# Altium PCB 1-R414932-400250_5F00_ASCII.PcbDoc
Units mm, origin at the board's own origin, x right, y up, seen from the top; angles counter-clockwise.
Board outline 46.04 x 15.24 mm, 2 copper layers (Top Layer, Bottom Layer), stack 1.97 mm thick; 97 components, 64 nets, 370 pads, 105 vias.
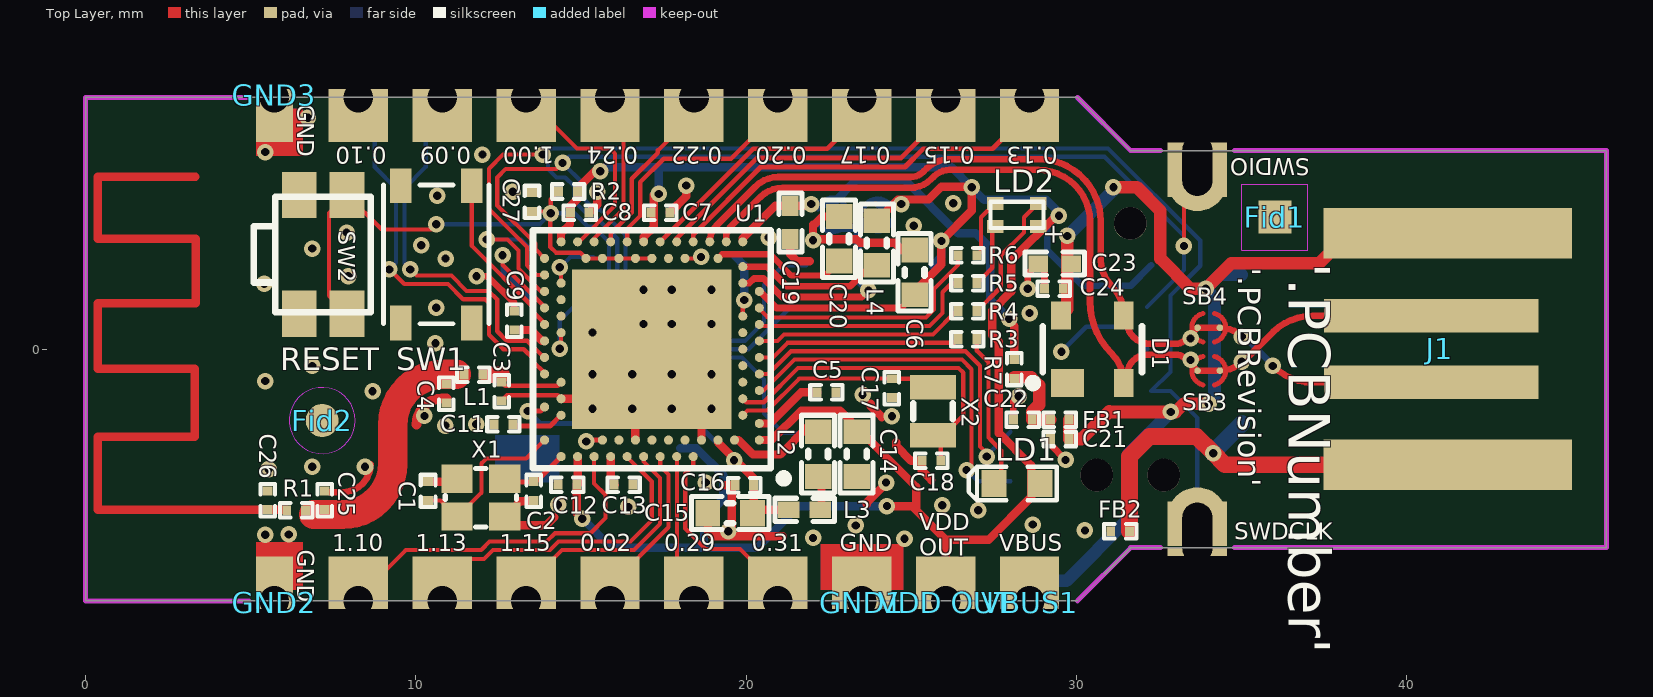
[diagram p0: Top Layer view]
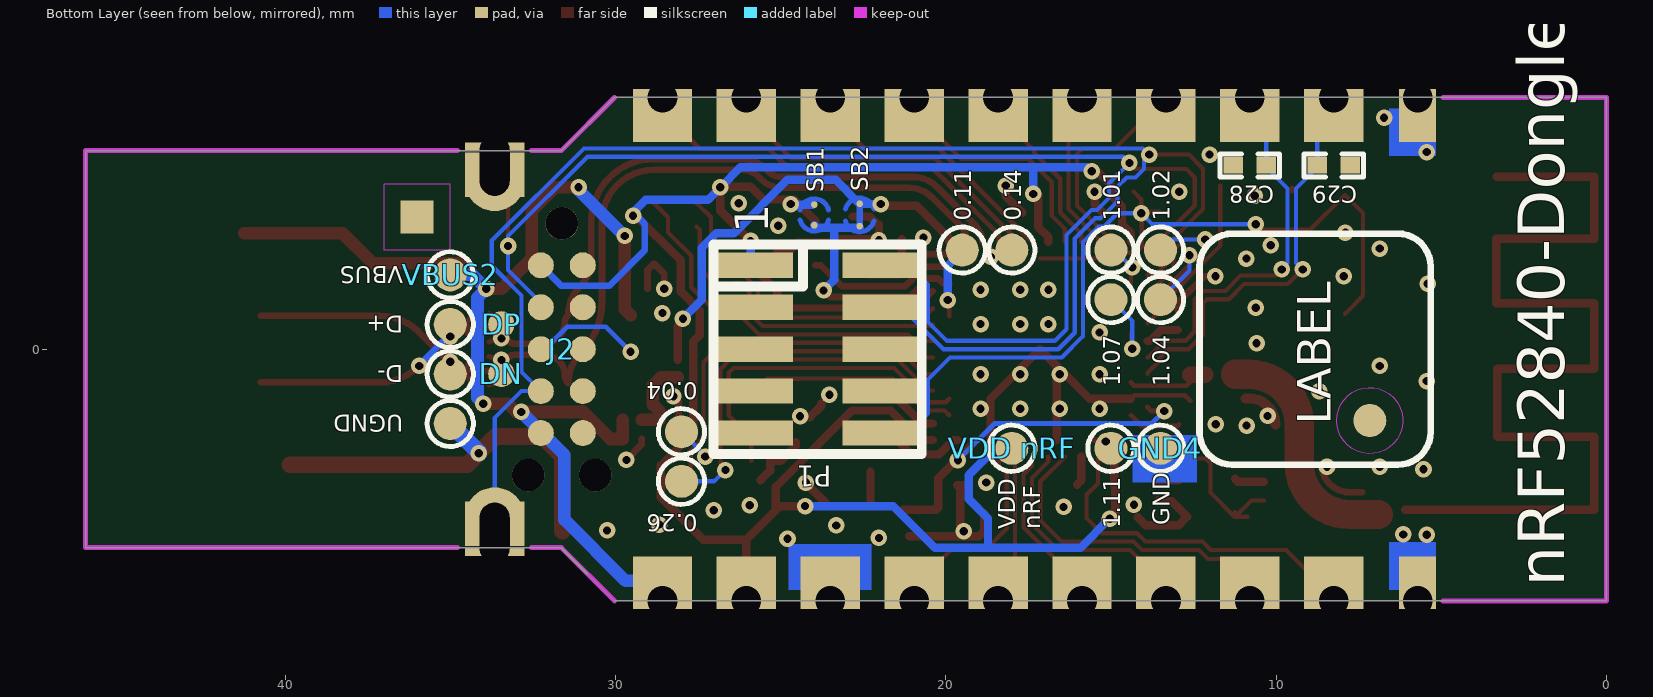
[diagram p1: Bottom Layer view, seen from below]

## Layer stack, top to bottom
Top Solder: solder mask 0.05, Solder Resist Halogen-Free, Dk 3.5
Top Layer: signal copper 0.035
Dielectric1: core 1.9, FR-4 Halogen-Free, Dk 4.8
Bottom Layer: signal copper 0.035
Bottom Solder: solder mask 0.05, Solder Resist Halogen-Free, Dk 3.5

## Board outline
0,-7.62 0,7.62 30.027,7.62 31.637,6.01 46.039,6.01 46.039,-6.01 31.637,-6.01 30.027,-7.62

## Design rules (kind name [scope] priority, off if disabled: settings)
AssemblyTestPointUsage [All] p0: scope1count=1 scope1_0_kind=Board scope1_0_value=Board scope2count=1 scope2_0_kind=Board scope2_0_value=Board commentlength=0
AssemblyTestpoint [All] p0: scope1count=1 scope1_0_kind=Board scope1_0_value=Board scope2count=1 scope2_0_kind=Board scope2_0_value=Board commentlength=0
Clearance [All] p0: scope1count=1 scope1_0_kind=Board scope1_0_value=Board scope2count=1 scope2_0_kind=Board scope2_0_value=Board commentlength=0 gap=0.127
Clearance SB_Clearance [All] p0: scope1count=1 scope1_0_kind=Footprint scope1_0_value=Solderbridge scope2count=1 scope2_0_kind=Board scope2_0_value=Board commentlength=0 gap=0.127
Clearance Polygon_Clearance [All] p0 off: scope1count=1 scope1_0_kind=Board scope1_0_value=Board scope2count=1 scope2_0_kind=Board scope2_0_value=Board commentlength=190 gap=0.203 // Protel DXP Scope 1 Expression Was: (InNamedPolygon('Top_Layer-GND')) or (InNamedPolygon('Bottom_Layer-GND')) or (InNamedPolygon('Mid_Layer_1-GND')) or (InNamedPolygon('Mid_Layer_2-GND'))
Clearance NPTH [All] p0 off: scope1count=1 scope1_0_kind=Board scope1_0_value=Board scope2count=1 scope2_0_kind=Board scope2_0_value=Board commentlength=71 gap=0.229 // Protel DXP Scope 1 Expression Was: Not PadIsPlated And HoleSize > 0
Clearance ANT_Clerance [All] p0 off: scope1count=1 scope1_0_kind=Board scope1_0_value=Board scope2count=1 scope2_0_kind=Board scope2_0_value=Board commentlength=66 gap=0.127 // Protel DXP Scope 1 Expression Was: InNet('ANT') or InNet('RF')
Clearance ANT_Clerance [InNet('ANT') or InNet('RF')] p1: gap=0.127 ignorepadtopadclearanceinfootprint=FALSE except(0: Arc-Hole Track-Hole SMDPad-Hole THPad-Hole Via-Hole Fill-Hole Poly-Hole Region-Hole Text-Hole)
Clearance NPTH [Not PadIsPlated And HoleSize > 0] p2: gap=0.229 ignorepadtopadclearanceinfootprint=FALSE except(0: Arc-Hole Track-Hole SMDPad-Hole THPad-Hole Via-Hole Fill-Hole Poly-Hole Region-Hole Text-Hole)
Clearance Polygon_Clearance [(InNamedPolygon('Top_Layer-GND')) or (InNamedPolygon('Bottom_Layer-GND')) or (InNamedPolygon('Mid_Layer_1-GND')) or (InNamedPolygon('Mid_Layer_2-GND'))] p3: gap=0.203 ignorepadtopadclearanceinfootprint=FALSE
Clearance SB_Clearance [HasFootprint('Solderbridge')] p4: gap=0.127 ignorepadtopadclearanceinfootprint=FALSE except(0: Arc-Hole Track-Hole SMDPad-Hole THPad-Hole Via-Hole Fill-Hole Poly-Hole Region-Hole Text-Hole)
Clearance [All] p5: gap=0.127 ignorepadtopadclearanceinfootprint=FALSE
ComponentClearance [All] p0 off: scope1count=1 scope1_0_kind=Board scope1_0_value=Board scope2count=1 scope2_0_kind=Board scope2_0_value=Board commentlength=0 gap=0.254 collisioncheckmode=3
ComponentClearance [All] p1 off: gap=0.254 collisioncheckmode=3 verticalgap=0.254 showdistances=FALSE
DiffPairsRouting [All] p0: scope1count=1 scope1_0_kind=Board scope1_0_value=Board scope2count=1 scope2_0_kind=Board scope2_0_value=Board commentlength=0
DiffPairsRouting [All] p1: maxlimit=0.127 minlimit=0.127 mostfreqgap=0.127 toplayer_minwidth=0.2 toplayer_maxwidth=0.2 toplayer_prefwidth=0.2 bottomlayer_minwidth=0.2 bottomlayer_maxwidth=0.2 bottomlayer_prefwidth=0.2 maxuncoupledlength=12.7
FabricationTestPointUsage TestPointUsage [All] p0: scope1count=1 scope1_0_kind=Board scope1_0_value=Board scope2count=1 scope2_0_kind=Board scope2_0_value=Board commentlength=0 valid=0 allowmultiple=FALSE
FabricationTestPointUsage TestPointUsage [All] p1: valid=0 allowmultiple=FALSE
FabricationTestpoint Testpoint [All] p0: scope1count=1 scope1_0_kind=Board scope1_0_value=Board scope2count=1 scope2_0_kind=Board scope2_0_value=Board commentlength=0 side=3 testpointundercomponent=TRUE minsize=1.016 maxsize=2.54 preferedsize=1.524 minholesize=0 maxholesize=1.016 preferedholesize=0.813 testpointgrid=0.025
FabricationTestpoint Testpoint [All] p1: side=3 testpointundercomponent=TRUE minsize=1.016 maxsize=2.54 preferedsize=1.524 minholesize=0 maxholesize=1.016 preferedholesize=0.813 testpointgrid=0.025 allowsidetop=TRUE allowsidebottom=TRUE usegrid=TRUE gridtolerance=0
FanoutControl Fanout_Default [All] p0: scope1count=1 scope1_0_kind=Board scope1_0_value=Board scope2count=1 scope2_0_kind=Board scope2_0_value=Board commentlength=30 // Fanout_Default (Default Rule)
FanoutControl Fanout_Small [All] p0 off: scope1count=1 scope1_0_kind=Board scope1_0_value=Board scope2count=1 scope2_0_kind=Board scope2_0_value=Board commentlength=84 // Protel DXP Scope 1 Expression Was: (CompPinCount < 5)   Fanout_Small (Default Rule)
FanoutControl Fanout_SOIC [All] p0 off: scope1count=1 scope1_0_kind=Board scope1_0_value=Board scope2count=1 scope2_0_kind=Board scope2_0_value=Board commentlength=71 // Protel DXP Scope 1 Expression Was: IsSOIC   Fanout_SOIC (Default Rule)
FanoutControl Fanout_LCC [All] p0 off: scope1count=1 scope1_0_kind=Board scope1_0_value=Board scope2count=1 scope2_0_kind=Board scope2_0_value=Board commentlength=69 // Protel DXP Scope 1 Expression Was: IsLCC   Fanout_LCC (Default Rule)
FanoutControl Fanout_BGA [All] p0 off: scope1count=1 scope1_0_kind=Board scope1_0_value=Board scope2count=1 scope2_0_kind=Board scope2_0_value=Board commentlength=69 // Protel DXP Scope 1 Expression Was: IsBGA   Fanout_BGA (Default Rule)
Height [All] p0 off: scope1count=1 scope1_0_kind=Board scope1_0_value=Board scope2count=1 scope2_0_kind=Board scope2_0_value=Board commentlength=0
Height [All] p1 off: minheight=0 maxheight=25.4 prefheight=12.7
HoleSize [All] p0: scope1count=1 scope1_0_kind=Board scope1_0_value=Board scope2count=1 scope2_0_kind=Board scope2_0_value=Board commentlength=0 absolutevalues=TRUE maxlimit=2.54 minlimit=0.1 maxpercent=80.000 minpercent=20.000
HoleSize [All] p1: absolutevalues=TRUE maxlimit=2.54 minlimit=0.1 maxpercent=80.000 minpercent=20.000
HoleToHoleClearance [All] p0: scope1count=1 scope1_0_kind=Board scope1_0_value=Board scope2count=1 scope2_0_kind=Board scope2_0_value=Board commentlength=0
LayerPairs [All] p0: scope1count=1 scope1_0_kind=Board scope1_0_value=Board scope2count=1 scope2_0_kind=Board scope2_0_value=Board commentlength=0 enforce=TRUE
MinimumAnnularRing [All] p0 off: scope1count=1 scope1_0_kind=Board scope1_0_value=Board scope2count=1 scope2_0_kind=Board scope2_0_value=Board commentlength=0 minimumring=0.152
MinimumAnnularRing [All] p1 off: minimumring=0.152
MinimumSolderMaskSliver [All] p0: scope1count=1 scope1_0_kind=Board scope1_0_value=Board scope2count=1 scope2_0_kind=Board scope2_0_value=Board commentlength=0
NetAntennae [All] p0: scope1count=1 scope1_0_kind=Board scope1_0_value=Board scope2count=1 scope2_0_kind=Board scope2_0_value=Board commentlength=0
PasteMaskExpansion [All] p0: scope1count=1 scope1_0_kind=Board scope1_0_value=Board scope2count=1 scope2_0_kind=Board scope2_0_value=Board commentlength=0 expansion=0
PlaneClearance [All] p0: scope1count=1 scope1_0_kind=Board scope1_0_value=Board scope2count=1 scope2_0_kind=Board scope2_0_value=Board commentlength=0 clearance=0.508
PlaneConnect [All] p0: scope1count=1 scope1_0_kind=Board scope1_0_value=Board scope2count=1 scope2_0_kind=Board scope2_0_value=Board commentlength=0 planeconnectstyle=Relief reliefexpansion=0.508 reliefentries=4 reliefconductorwidth=0.254 reliefairgap=0.254
PolygonConnect [All] p0: scope1count=1 scope1_0_kind=Board scope1_0_value=Board scope2count=1 scope2_0_kind=Board scope2_0_value=Board commentlength=0 connectstyle=Relief reliefconductorwidth=0.254 reliefentries=4 polygonreliefangle="90 Angle"
PolygonConnect PolygonConnect_1 [All] p0 off: scope1count=1 scope1_0_kind=Board scope1_0_value=Board scope2count=1 scope2_0_kind=Board scope2_0_value=Board commentlength=59 connectstyle=Direct reliefconductorwidth=0.254 reliefentries=4 polygonreliefangle="90 Angle" // Protel DXP Scope 1 Expression Was: isVia and innet(gnd)
PolygonConnect PolygonConnect_1 [isVia and innet(gnd)] p1: connectstyle=Direct reliefconductorwidth=0.254 reliefentries=4 polygonreliefangle="90 Angle" airgapwidth=0.254
PolygonConnect [All] p2: connectstyle=Relief reliefconductorwidth=0.254 reliefentries=4 polygonreliefangle="90 Angle" airgapwidth=0.254
RoutingCorners [All] p0: scope1count=1 scope1_0_kind=Board scope1_0_value=Board scope2count=1 scope2_0_kind=Board scope2_0_value=Board commentlength=0 cornerstyle=45-Degree minsetback=2.54 maxsetback=2.54
RoutingLayers [All] p0: scope1count=1 scope1_0_kind=Board scope1_0_value=Board scope2count=1 scope2_0_kind=Board scope2_0_value=Board commentlength=0 top layer=Automatic bottom layer=Automatic
RoutingPriority [All] p0: scope1count=1 scope1_0_kind=Board scope1_0_value=Board scope2count=1 scope2_0_kind=Board scope2_0_value=Board commentlength=0
RoutingTopology [All] p0: scope1count=1 scope1_0_kind=Board scope1_0_value=Board scope2count=1 scope2_0_kind=Board scope2_0_value=Board commentlength=0 topology=Shortest
RoutingVias [All] p0: scope1count=1 scope1_0_kind=Board scope1_0_value=Board scope2count=1 scope2_0_kind=Board scope2_0_value=Board commentlength=0 holewidth=0.25 width=0.5 viastyle="Through Hole" minholewidth=0.1 minwidth=0.3 maxholewidth=0.305 maxwidth=0.61
RoutingVias [All] p1: holewidth=0.25 width=0.5 viastyle="Through Hole" minholewidth=0.1 minwidth=0.3 maxholewidth=0.305 maxwidth=0.61
ShortCircuit [All] p0: scope1count=1 scope1_0_kind=Board scope1_0_value=Board scope2count=1 scope2_0_kind=Board scope2_0_value=Board commentlength=0 allowed=FALSE
SilkToBoardRegionClearance [All] p0: scope1count=1 scope1_0_kind=Board scope1_0_value=Board scope2count=1 scope2_0_kind=Board scope2_0_value=Board commentlength=0
SilkToSilkClearance [All] p0: scope1count=1 scope1_0_kind=Board scope1_0_value=Board scope2count=1 scope2_0_kind=Board scope2_0_value=Board commentlength=0
SilkToSolderMaskClearance SilkscreenOverComponentPads [All] p0 off: scope1count=1 scope1_0_kind=Board scope1_0_value=Board scope2count=1 scope2_0_kind=Board scope2_0_value=Board commentlength=44 // Protel DXP Scope 1 Expression Was: IsPad
SilkToSolderMaskClearance SilkscreenOverComponentPads [IsPad] p1: minsilkscreentomaskgap=0.254 clearancetoexposedcopper=TRUE
SolderMaskExpansion [All] p0: scope1count=1 scope1_0_kind=Board scope1_0_value=Board scope2count=1 scope2_0_kind=Board scope2_0_value=Board commentlength=0 expansion=0.076
SolderMaskExpansion [All] p1: expansion=0.076 istentingtop=FALSE
UnRoutedNet [All] p0: scope1count=1 scope1_0_kind=Board scope1_0_value=Board scope2count=1 scope2_0_kind=Board scope2_0_value=Board commentlength=0
UnpouredPolygon [All] p0: scope1count=1 scope1_0_kind=Board scope1_0_value=Board scope2count=1 scope2_0_kind=Board scope2_0_value=Board commentlength=0
Width [All] p0: scope1count=1 scope1_0_kind=Board scope1_0_value=Board scope2count=1 scope2_0_kind=Board scope2_0_value=Board commentlength=0 maxlimit=2.54 minlimit=0.127 preferedwidth=0.152
Width [All] p1: maxlimit=2.54 minlimit=0.127 preferedwidth=0.152 minimp=50.000000 maximp=50.000000 favimp=50.000000
23 further rules are at their usual default settings.

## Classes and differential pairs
differential pair " ": +D_P -D_N

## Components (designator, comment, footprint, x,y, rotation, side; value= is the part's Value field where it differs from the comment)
0.02 "CH" Castellated_Hole_0.9mm 15.875,-7.62 r0 top locked
0.04 "Ø1.0mm,SMD" TP_SMD_D1.0mm#1 28,-2.5 r180 bottom locked
0.09 "CH" Castellated_Hole_0.9mm 10.795,7.62 r180 top locked
0.10 "CH" Castellated_Hole_0.9mm 8.255,7.62 r180 top locked
0.11 "Ø1.0mm,SMD" TP_SMD_D1.0mm#1 19.5,3 r180 bottom locked
0.13 "CH" Castellated_Hole_0.9mm 28.575,7.62 r180 top locked
0.14 "Ø1.0mm,SMD" TP_SMD_D1.0mm#1 18,3 r180 bottom locked
0.15 "CH" Castellated_Hole_0.9mm 26.035,7.62 r180 top locked
0.17 "CH" Castellated_Hole_0.9mm 23.495,7.62 r180 top locked
0.20 "CH" Castellated_Hole_0.9mm 20.955,7.62 r180 top locked
0.22 "CH" Castellated_Hole_0.9mm 18.415,7.62 r180 top locked
0.24 "CH" Castellated_Hole_0.9mm 15.875,7.62 r180 top locked
0.26 "Ø1.0mm,SMD" TP_SMD_D1.0mm#1 28,-4 r180 bottom locked
0.29 "CH" Castellated_Hole_0.9mm 18.415,-7.62 r0 top locked
0.31 "CH" Castellated_Hole_0.9mm 20.955,-7.62 r0 top locked
1.00 "CH" Castellated_Hole_0.9mm 13.335,7.62 r180 top locked
1.01 "Ø1.0mm,SMD" TP_SMD_D1.0mm#1 15,3 r180 bottom locked
1.02 "Ø1.0mm,SMD" TP_SMD_D1.0mm#1 13.5,3 r180 bottom locked
1.04 "Ø1.0mm,SMD" TP_SMD_D1.0mm#1 13.5,1.5 r180 bottom locked
1.07 "Ø1.0mm,SMD" TP_SMD_D1.0mm#1 15,1.5 r180 bottom locked
1.10 "CH" Castellated_Hole_0.9mm 8.255,-7.62 r0 top locked
1.11 "Ø1.0mm,SMD" TP_SMD_D1.0mm#1 15,-3 r180 bottom locked
1.13 "CH" Castellated_Hole_0.9mm 10.795,-7.62 r0 top locked
1.15 "CH" Castellated_Hole_0.9mm 13.335,-7.62 r0 top locked
C1 "12pF" CAPC0603X03L_C 10.367,-4.293 r90 top
C2 "12pF" CAPC0603X03L_C 13.568,-4.293 r270 top
C3 "0.8pF" CAPC0603X03L_C 12.593,-1.275 r90 top locked
C4 "0.5pF" CAPC0603X03L_C 10.922,-1.346 r90 top locked
C5 "100nF" CAPC0603X03L_C 22.428,-1.306 r0 top locked
C6 "4.7µF" CAPC1608X06L 25.095,2.326 r90 top locked
C7 "100nF" CAPC0603X03L_C 17.399,4.129 r0 top locked
C8 "100nF" CAPC0603X03L_C 14.961,4.129 r0 top locked
C9 "820pF" CAPC0603X03L_C 12.979,0.864 r90 top locked
C11 "100pF" CAPC0603X03L_C 12.65,-2.275 r180 top
C12 "100nF" CAPC0603X03L_C 14.584,-4.101 r180 top locked
C13 "N.C." CAPC0603X03L_C_NC 16.285,-4.101 r0 top locked
C14 "1.0µF" CAPC1608X06L 23.343,-3.175 r270 top locked
C15 "1.0µF" CAPC1608X06L 19.511,-4.965 r0 top locked
C16 "47nF" CAPC0603X03L_C 19.939,-4.115 r180 top locked
C17 "12pF" CAPC0603X03L_C 24.409,-1.179 r270 top locked
C18 "12pF" CAPC0603X03L_C 25.603,-3.378 r180 top locked
C19 "4.7µF" CAPC1005X04L 21.336,3.835 r270 top locked
C20 "4.7µF" CAPC1608X06L 22.809,3.342 r90 top locked
C21 "10nF" CAPC0603X03L_C 29.489,-2.718 r0 top locked
C22 "100nF" CAPC0603X03L_C 28.372,-2.134 r0 top locked
C23 "4.7µF" CAPC1005X04L 29.337,2.591 r0 top locked
C24 "100nF" CAPC0603X03L_C 29.312,1.829 r0 top locked
C25 "N.C." CAPC0603X03L_C_NC 7.239,-4.572 r90 top locked
C26 "1.5pF" CAPC0603X03L_C 5.512,-4.572 r270 top locked
C27 "100nF" CAPC0603X03L_C 13.513,4.458 r270 top locked
C28 "N.C." CAPC1005X04L_NC 10.795,5.563 r180 bottom locked
C29 "N.C." CAPC1005X04L_NC 8.255,5.563 r180 bottom locked
D1 "PRTR5V0U2X" SOT190P230X110-4L 30.48,0 r90 top locked
D+ "Ø1.0mm,SMD" TP_SMD_D1.0mm#1 35,0.75 r180 bottom locked
D- "Ø1.0mm,SMD" TP_SMD_D1.0mm#1 35,-0.75 r180 bottom locked
DN "Ø1.0mm,SMD" TP_SMD_D1.0mm#2 33.45,-0.75 r270 bottom locked
DP "Ø1.0mm,SMD" TP_SMD_D1.0mm#2 33.45,0.75 r270 bottom locked
FB1 "120R/0.85A" INDC0603X03L_C 29.489,-2.134 r180 top locked
FB2 "120R/0.85A" INDC0603X03L_C 31.318,-5.512 r180 top locked
Fid1 "Fiducial mark" Fiducial_Square 36,4 r0 top locked
Fid2 "Fiducial mark" Fiducial 7.163,-2.159 r0 top locked
GND1 "GND" Castellated_Hole_0.9mm 23.495,-7.62 r0 top locked
GND2 "GND" Castellated_Hole_0.9mm_S 5.715,-7.62 r0 top locked
GND3 "GND" Castellated_Hole_0.9mm_S 5.715,7.62 r180 top locked
GND4 "GND" TP_SMD_D1.0mm#1 13.5,-3 r180 bottom locked
J1 "USB-A" USB-A-PCB 41.039,0.01 r180 top locked
J2 "TC2050-IDC" TC2050-IDC-NLFP 31.623,0 r270 bottom locked
L1 "4.7nH" INDC0603X03L_C 11.739,-0.771 r180 top locked
L2 "10µH" INDC1608X06L 22.174,-3.175 r90 top locked
L3 "15nH" INDC1005X04L 21.768,-4.862 r0 top locked
L4 "10µH" INDC1608X06L 23.952,3.215 r270 top locked
LD1 "L0603G" LED_0603_G 28.194,-4.064 r0 top locked
LD2 "LED RGB" LED_RGB_0603 28.194,4.064 r90 top locked
P1 "Pin Header 2x5, 1.27mm" HDR_2x5-SMD-1.27mm-NC 23.876,0 r270 bottom locked
R1 "0R" RESC0603X03L_C 6.375,-4.877 r180 top locked
R2 "10k" RESC0603X03L_C 14.605,4.775 r0 top locked
R3 "220R" RESC0603X03L_C 26.695,0.305 r0 top locked
R4 "1k2" RESC0603X03L_C 26.695,1.151 r0 top locked
R5 "2k2" RESC0603X03L_C 26.695,1.998 r0 top locked
R6 "390R" RESC0603X03L_C 26.695,2.845 r0 top locked
R7 "4R7" RESC0603X03L_C 28.114,-0.6 r270 top
SB1 "Solderbridge" Solderbridge 23.978,4.064 r270 bottom locked
SB2 "Solderbridge" Solderbridge_Shorted 22.606,4.064 r90 bottom locked net-tie
SB3 "Solderbridge" Solderbridge_Shorted 34,-0.65 r0 top locked net-tie
SB4 "Solderbridge" Solderbridge_Shorted 34,0.65 r0 top locked net-tie
SW1 "PB SW" C&K_PTS810 10.617,2.87 r270 top locked
SW2 "PTS840 GK SMTR LFS" EVQP7A_J_B_K 7.188,2.87 r270 top locked
SWDCLK "CH" Castellated_Hole_0.9mm_D 33.655,-5.56 r0 top locked
SWDIO "CH" Castellated_Hole_0.9mm_D 33.655,5.56 r180 top locked
U1 "nRF52840-QIAA" AQFN50P700X700X85_HS-74N 17.145,0 r180 top locked
UGND "Ø1.0mm,SMD" TP_SMD_D1.0mm#1 35,-2.25 r180 bottom locked
VBUS1 "VBUS" Castellated_Hole_0.9mm 28.575,-7.62 r0 top locked
VBUS2 "VBUS" TP_SMD_D1.0mm#1 35,2.25 r180 bottom locked
"VDD nRF" "Ø1.0mm,SMD" TP_SMD_D1.0mm#1 18,-3 r180 bottom locked
"VDD OUT" "CH" Castellated_Hole_0.9mm 26.035,-7.62 r0 top locked
X1 "32MHz" BT-XTAL_2016 11.967,-4.496 r0 top
X2 "32.768kHz" XTAL_2012 25.654,-1.88 r270 top locked

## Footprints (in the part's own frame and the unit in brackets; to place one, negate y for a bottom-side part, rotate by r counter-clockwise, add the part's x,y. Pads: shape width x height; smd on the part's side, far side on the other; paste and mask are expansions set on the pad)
AQFN50P700X700X85_HS-74N [mm] "AQFN, 73-Leads, Body 7.00x7.00mm, Pitch 0.50mm, Thermal Pad 4.95x4.95mm, IPC Medium Density"
  rect 4.83x4.83 smd paste-5 mask+0: 74(0,0)
  round 0.275 smd paste-5 mask+0: A8(-1.25,3.25) A10(-0.75,3.25) A12(-0.25,3.25) A14(0.25,3.25) A16(0.75,3.25) A18(1.25,3.25) A20(1.75,3.25) A22(2.25,3.25) A23(2.75,3.25) AA24(3.25,-2.25) AB2(-2.75,-2.5) AC5(-2,-2.75) AC9(-1,-2.75) AC11(-0.5,-2.75) AC13(0,-2.75) AC15(0.5,-2.75) AC17(1,-2.75) AC19(1.5,-2.75) AC21(2,-2.75) AC24(3.25,-2.75) AD2(-2.75,-3.25) AD4(-2.25,-3.25) AD6(-1.75,-3.25) AD8(-1.25,-3.25) AD10(-0.75,-3.25) AD12(-0.25,-3.25) AD14(0.25,-3.25) AD16(0.75,-3.25) AD18(1.25,-3.25) AD20(1.75,-3.25) AD22(2.25,-3.25) AD23(2.75,-3.25) B1(-3.25,2.75) B3(-2.5,2.75) B5(-2,2.75) B7(-1.5,2.75) B9(-1,2.75) B11(-0.5,2.75) B13(0,2.75) B15(0.5,2.75) B17(1,2.75) B19(1.5,2.75) B24(3.25,2.75) C1(-3.25,2.25) D2(-2.75,2) D23(2.75,2) E24(3.25,1.75) F2(-2.75,1.5) F23(2.75,1.5) G1(-3.25,1.25) H2(-2.75,1) H23(2.75,1) J1(-3.25,0.75) J24(3.25,0.75) K2(-2.75,0.5) L1(-3.25,0.25) L24(3.25,0.25) M2(-2.75,0) N1(-3.25,-0.25) N24(3.25,-0.25) P2(-2.75,-0.5) P23(2.75,-0.5) R1(-3.25,-0.75) R24(3.25,-0.75) T2(-2.75,-1) T23(2.75,-1) U1(-3.25,-1.25) U24(3.25,-1.25) V23(2.75,-1.5) W1(-3.25,-1.75) W24(3.25,-1.75) Y2(-2.75,-2) Y23(2.75,-2)
  silkscreen extent -4.11,-3.6 3.6,4.04
BT-XTAL_2016 [mm] "Crystal 2.0 x 1.6 mm"
  rect 0.95x0.85 smd: 1(-0.725,-0.575) 2(0.725,-0.575) 3(0.725,0.575) 4(-0.725,0.575)
  silkscreen extent -1.08,-0.88 1.08,0.88
C&K_PTS810 [mm] "Microminiature SMT Top Actuated"
  rect 1.05x0.65 smd: 0(2.075,1.075) 1(-2.075,1.075) 2(-2.075,-1.075) 2(2.075,-1.075)
  silkscreen extent -2.1,-1.6 2.1,1.6
CAPC0603X03L_C [mm] "Chip Capacitor, 2-Leads, Body 0.6x0.3mm, IPC High Density"
  rect 0.27x0.3 smd: 1(-0.285,0) 2(0.285,0)
  silkscreen extent -0.49,-0.22 0.49,0.22
CAPC0603X03L_C_NC [mm] "Chip Capacitor, 2-Leads, Body 0.6x0.3mm, IPC High Density"
  rect 0.27x0.3 smd mask+0: 1(-0.285,0) 2(0.285,0)
  silkscreen extent -0.49,-0.22 0.49,0.22
CAPC1005X04L [mm] "Chip Capacitor, 2-Leads, Body 1.0x0.5mm, IPC High Density"
  rect 0.6x0.5 smd: 1(-0.5,0) 2(0.5,0)
  silkscreen extent -0.9,-0.35 0.9,0.35
CAPC1005X04L_NC [mm] "Chip Capacitor, 2-Leads, Body 1.0x0.5mm, IPC High Density"
  rect 0.6x0.5 smd: 1(-0.5,0) 2(0.5,0)
  silkscreen extent -0.9,-0.35 0.9,0.35
CAPC1608X06L [mm] "Chip Capacitor, 2-Leads, Body 1.6x0.8mm, IPC High Density"
  rect 0.75x0.8 smd: 1(-0.675,0) 2(0.675,0)
  silkscreen extent -1.17,-0.5 1.17,0.5
Castellated_Hole_0.9mm [mm]
  rect 1.8x0.25 hole 0.25 square: 1(0,-0.126)
  rect 1.8x1.35 hole 0.9 copper offset 0,0.675: 1(0,0)
Castellated_Hole_0.9mm_D [mm]
  rect 1.8x0.25 hole 0.25 square: 1(0,-0.576)
  rect 1.8x1.35 hole 0.9 slot 1.83 at 90 deg copper offset 0,0.275: 1(0,0)
  round 1.8 smd paste-5: 1(0,0.48)
  round 1.8 smd far side paste-5: 1(0,0.48)
Castellated_Hole_0.9mm_S [mm]
  rect 1.118x0.25 hole 0.25 square: 1(0,-0.126)
  rect 1.118x1.35 hole 0.9 copper offset 0,0.675: 1(0,0)
EVQP7A_J_B_K [mm] "Subminiature Side Actuated Tact Switch for SMT"
  rect 1.4x1.05 smd: 1(-1.8,0.725) 1(1.8,0.725) 2(-1.8,-0.725) 2(1.8,-0.725)
  silkscreen extent -1.75,-2.1 1.75,1.45
Fiducial [mm] "Fiducial Mark"
  round 1 smd paste+0 mask+0: 0(0,0)
  round 1 smd far side paste+0 mask+0: 0(0,0)
  Top Layer keep-out circle w0.01: c0,0 r1
  Bottom Layer keep-out circle w0.01: c0,0 r1
Fiducial_Square [mm] "Fiducial Mark"
  rect 1x1 smd paste-10 mask+0: 0(0,0)
  rect 1x1 smd far side paste-10 mask+0: 0(0,0)
  Top Layer keep-out lines w0.01: -1,-1 1,-1 1,1 -1,1 -1,-1
  Bottom Layer keep-out lines w0.01: -1,-1 -1,1 1,1 1,-1 -1,-1
HDR_2x5-SMD-1.27mm-NC [mm] "SMT MICRO HEADER, (1,27) .050\""
  rect 0.76x2.4 smd: 1(-2.54,-1.95) 2(-2.54,1.95) 3(-1.27,-1.95) 4(-1.27,1.95) 5(0,-1.95) 6(0,1.95) 7(1.27,-1.95) 8(1.27,1.95) 9(2.54,-1.95) 10(2.54,1.95)
  silkscreen extent -3.18,-3.15 3.18,3.15
INDC0603X03L_C [mm] "Chip Inductor, 2-Leads, Body 0.6x0.3mm, IPC High Density"
  rect 0.27x0.3 smd: 1(-0.285,0) 2(0.285,0)
  silkscreen extent -0.49,-0.22 0.49,0.22
INDC1005X04L [mm] "Chip Inductor, 2-Leads, Body 1.0x0.5mm, IPC High Density"
  rect 0.65x0.5 smd: 1(-0.475,0) 2(0.475,0)
  silkscreen extent -0.9,-0.35 0.9,0.35
INDC1608X06L [mm] "Chip Inductor, 2-Leads, Body 1.6x0.8mm, IPC High Density"
  rect 0.75x0.8 smd: 1(-0.675,0) 2(0.675,0)
  silkscreen extent -1.17,-0.5 1.17,0.5
LED_0603_G [mil] "SMD Super Bright LED, GREEN"
  rect 30x32 smd: 1(-27.5,0) 2(27.5,0)
  silkscreen extent -58,-20 48,20
LED_RGB_0603 [mm]
  rect 0.4x0.5 smd paste+0: 1(0.35,-0.65) 2(-0.35,0.65) 3(0.35,0.65) 4(-0.35,-0.65)
  silkscreen extent -0.4,-0.8 0.4,0.8
RESC0603X03L_C [mm] "Chip Resistor, 2-Leads, Body 0.6x0.3mm, IPC High Density"
  rect 0.27x0.3 smd: 1(-0.285,0) 2(0.285,0)
  silkscreen extent -0.49,-0.22 0.49,0.22
Solderbridge [mm]
  round 0.2 smd paste-10: 1(-0.312,0) 2(0.312,0)
  Top Layer lines w0.152: 0.153,0.431 cw(c0.042,0) 0.383,0.286 cw(c0.042,0) 0.478,-0.088 cw(c0.042,0) 0.153,-0.431 ; -0.153,0.431 ccw(c-0.042,0) -0.312,-0.353 ccw(c-0.042,0) -0.153,-0.431
Solderbridge_Shorted [mm]
  round 0.2 smd paste-10: 1(-0.338,0) 2(0.338,0)
  Top Layer lines w0.152: -0.178,-0.431 cw(c-0.068,0) -0.178,0.431 ; 0.178,-0.431 ccw(c0.068,0) 0.178,0.431
  Top Layer lines w0.203: -0.338,0 0.338,0
SOT190P230X110-4L [mm] "SOT143, 4-Leads, Body 3.0x2.5mm (max), Pitch 1.90mm, IPC High Density"
  rect 0.85x1 smd: 1(-1.025,0.75)
  rect 0.85x0.6 smd: 2(-1.025,-0.95) 3(1.025,-0.95) 4(1.025,0.95)
  silkscreen extent -1.15,-1.5 0.7,1.92
TC2050-IDC-NLFP [mil]
  round 39 hole 39 unplated mask+0: 0(-150,0) 0(150,-40) 0(150,40)
  round 31 smd paste-196.85: 1(-100,-25) 2(-50,-25) 3(0,-25) 4(50,-25) 5(100,-25) 6(100,25) 7(50,25) 8(0,25) 9(-50,25) 10(-100,25)
TP_SMD_D1.0mm#1 [mm] "Test point - pad 1.0mm"
  round 1 smd paste-5: 1(0,0)
  silkscreen extent -0.7,-0.7 0.7,0.7
TP_SMD_D1.0mm#2 [mm] "Test point - pad 1.0mm"
  round 0.8 smd paste-5: 1(0,0)
USB-A-PCB [mil]
  rect 296x60 smd paste-196.85: 1(-7.87,-137.8) 4(-7.87,138)
  rect 256x40 smd paste-196.85: 2(12,-39.37) 3(12,40)
XTAL_2012 [mm] "XTAL SMD 2.0 x 1.2 mm"
  rect 0.75x1.4 smd: 1(-0.725,0) 2(0.725,0)
  silkscreen extent -0.24,-0.6 0.24,0.6

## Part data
0.02 0.09 0.10 0.13 0.15 0.17 0.20 0.22 0.24 0.29 0.31 1.00 1.10 1.13 1.15 GND1 VBUS1 "VDD OUT": library part "Castellated Hole 0.9mm", "Castellated Hole 0.9mm"
0.04 0.11 0.14 0.26 1.01 1.02 1.04 1.07 1.11 D+ D- DN DP GND4 UGND VBUS2 "VDD nRF": library part TP_SMD_Ø1.0MM, "1.0mm circular SMD testpad"
C1 C2 C17 C18: library part C0201-12p, "Capacitor, NP0, ±2%"
C3: library part C0201-0.8p, "Capacitor, NP0, ±0.05pF, 50V"
C4: library part C0201-0.5p, "Capacitor, NP0, ±0.05pF"
C5 C7 C8 C12 C22 C24 C27: library part C0201-100n, "Capacitor, X5R, ±10%"
C6 C20: library part C0603-4µ7, "Capacitor, X5R, ±10%"
C9: library part C0201-820p, "Capacitor, X7R, ±10%"
C11: library part C0201-100p, "Capacitor, NP0, ±2%, 25V"
C13 C25: library part C0201-N.C., "Not mounted"
C14 C15: library part C0603-1µ0, "Capacitor, X7R, ±10%"
C16: library part C0201-47n, "Capacitor, X5R, ±10%"
C19 C23: library part C0402-4µ7, "Capacitor, X5R, ±20%"
C21: library part C0201-10n, "Capacitor, X7R, ±10%"
C26: library part C0201-1.5p, "Capacitor, NP0, ±0.1pF"
C28 C29: library part C0402-N.C., "Not mounted"
D1: "Ultra low capacitance double rail-to-rail ESD protection diode"
FB1 FB2: library part FB0201-120R@100M-850mA, "Ferrite Bead, 120 Ohm @ 100MHz, 850mA, 150 mOhm Max"
Fid1: library part Fid-Mark-Square, "Fiducial Mark"
Fid2: library part Fid-Mark, "Fiducial Mark"
GND2 GND3: library part "Castellated Hole 0.9mm_S", "Castellated Hole 0.9mm"
J1: library part USB-A-PCB, "USB-A PCB footprint"
J2: library part TC2050-IDC-NLFP, "CBL PLUG-OF-NAILS 10-PIN"
L1: library part L0201-4n7, "Inductor, 350mA, ±3%"
L2 L4: library part L0603-10µ, "Inductor, 80mA, ±10%"
L3: library part L0402-15n, "Inductor, 320mA, ±5%"
LD1: library part "VS 25C7M5", "LED, Green, 0603, 573nm, Vf=2.0V, 24mcd, - 40 to +85°C"
LD2: library part APHF1608LSEEQBDZGKC, "RGB LED 1.60 mm x 0.80 mm SMD"
P1: library part "Pin Header 2x5 SMD, 1.27mm, KS, N.C.", "Pin Header 2x5, 1.27mm (50mil), SMD, Keying Shroud"
R1: library part R0201-0R, "Resistor, ±5%, 0.05W"
R2: library part R0201-10k, "Resistor, ±1%, 0.05W"
R3: library part R0201-220, "Resistor, ±1%, 0.05W"
R4: library part R0201-1k2, "Resistor, ±1%, 0.05W"
R5: library part R0201-2k2, "Resistor, ±1%, 0.05W"
R6: library part R0201-390, "Resistor, ±1%, 0.05W"
R7: library part R0201-4R7, "Resistor, ±1%, 0.05W"
SB2 SB3 SB4: library part "Solderbridge Shorted", "Shorted Solderbridge"
SW1: library part "PTS810 SJK 250 SMTR LFS", "Tactile Switch, SPNO, SMD, 260gf, 4.2x3.2x2.5mm"
SW2: "Microminiature SMT Switch, Side Actuated"
SWDCLK SWDIO: library part "Castellated Hole 0.9mm_D", "Castellated Hole 0.9mm"
U1: library part nRF52840-QIAAF0, "Multi-protocol Bluetooth Low Energy, IEEE 802.15.4, ANT and 2.4GHz proprietary system-on-chip"
X1: library part XTAL_SMD2016_32MHz_8pF_Murata, "XTAL SMD 2016, 32MHz, Cl=8pF, Tol: ±10ppm, Stab: ±10ppm"
X2: library part XTAL_SMD2012_32.768kHz_9pF_Seiko, "XTAL SMD 2012, 32.768kHz, 9pF, ±20ppm"

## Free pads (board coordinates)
  rrect38% 0.253x0.253 on Top Paste: 0(13.895,-2.75) 0(13.895,-1.75) 0(13.895,-0.75) 0(13.895,-0.25) 0(13.895,0.25) 0(13.895,0.75) 0(13.895,1.25) 0(13.895,1.75) 0(13.895,2.25) 0(13.895,2.75) 0(14.395,-3.25) 0(14.395,-2) 0(14.395,-1.5) 0(14.395,-1) 0(14.395,0.5) 0(14.395,1) 0(14.395,1.5) 0(14.395,2) 0(14.395,3.25) 0(14.895,-3.25) 0(14.895,3.25) 0(15.145,2.75) 0(15.395,-3.25) 0(15.395,3.25) 0(15.645,-2.75) 0(15.645,2.75) 0(15.895,-3.25) 0(15.895,3.25) 0(16.145,-2.75) 0(16.145,2.75) 0(16.395,-3.25) 0(16.395,3.25) 0(16.645,-2.75) 0(16.645,2.75) 0(16.895,-3.25) 0(16.895,3.25) 0(17.145,-2.75) 0(17.145,2.75) 0(17.395,-3.25) 0(17.395,3.25) 0(17.645,-2.75) 0(17.645,2.75) 0(17.895,3.25) 0(17.9,-3.255) 0(18.145,-2.75) 0(18.145,2.75) 0(18.395,-3.25) 0(18.395,3.25) 0(18.645,-2.75) 0(18.895,3.25) 0(19.145,-2.75) 0(19.145,2.75) 0(19.395,3.25) 0(19.645,-2.75) 0(19.895,-2) 0(19.895,-1.5) 0(19.895,-1) 0(19.895,-0.5) 0(19.895,0) 0(19.895,0.5) 0(19.895,1) 0(19.895,2) 0(19.895,2.5) 0(19.895,3.25) 0(20.395,-2.75) 0(20.395,-2.25) 0(20.395,-1.25) 0(20.395,-0.75) 0(20.395,-0.25) 0(20.395,0.25) 0(20.395,0.75) 0(20.395,1.25) 0(20.404,1.75)
  rect 1.395x1.395 on Top Paste: 0(15.55,-1.595) 0(15.55,0) 0(15.55,1.595) 0(17.145,-1.595) 0(17.145,0) 0(17.145,1.595) 0(18.74,-1.595) 0(18.74,0) 0(18.74,1.595)
  round 1.8 smd paste-5: 3(33.655,-5.08) 3(33.655,5.08)
  round 1.8 smd far side paste-5: 3(33.655,-5.08) 3(33.655,5.08)

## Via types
v1: diameter 0.5, hole 0.25, Top Layer to Bottom Layer, tented both sides, 105 vias

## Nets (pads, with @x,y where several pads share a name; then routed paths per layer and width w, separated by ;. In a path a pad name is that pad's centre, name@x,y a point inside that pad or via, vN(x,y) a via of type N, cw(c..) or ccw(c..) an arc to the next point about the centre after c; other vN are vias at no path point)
ANT: C26.2 R1.2 | length 30.6
  Top Layer w0.254: 3.327,5.226 0.363,5.226 0.363,3.346 3.332,3.346 3.332,1.39 0.363,1.39 0.363,-0.591 3.307,-0.591 3.307,-2.648 0.363,-2.648 0.363,-4.866 R1.2@6.09,-4.866
D_N: D1.2 DN.1 SB3.1 U1.AD4 | length 21
  Top Layer w0.2: U1.AD4 19.395,3.404 cw(c19.814,3.404) 19.518,3.7 20.419,4.6 cw(c21.105,3.914) 21.105,4.885 24.964,4.885 ccw(c24.964,5.787) 25.601,5.149 25.682,5.23 cw(c26.162,4.75) 26.162,5.428 28.839,5.428 cw(c28.839,3.861) 30.407,3.861 30.407,1.445 ccw(c32.632,1.445) 31.059,-0.129 cw(c30.163,-1.025) D1.2 ccw(c31.189,-0.784) 31.53,-0.784 cw(c32.15,-0.784) 32.15,-0.163 33,-0.163 cw(c33,-0.588) 33.3,-0.288 SB3.1
  other v1: 33.45,-0.325
D_P: D1.3 DP.1 SB4.1 U1.AD6 | length 19.9
  Top Layer w0.2: U1.AD6 cw(c19.594,3.25) 19.1,3.744 20.283,4.927 ; 20.283,4.928 cw(c20.97,4.241) 20.97,5.212 24.964,5.212 ccw(c24.964,5.787) 25.37,5.38 25.451,5.461 cw(c26.162,4.75) 26.162,5.755 28.839,5.755 cw(c28.839,3.861) 30.734,3.861 30.734,2.705 ccw(c31.843,2.705) 31.059,1.921 cw(c30.163,1.025) D1.3 31.465,0.99 cw(c31.309,0.834) 31.53,0.834 ccw(c32.2,0.834) 32.2,0.163 33,0.163 ccw(c33,0.588) 33.3,0.288 SB4.1
  other v1: 33.45,0.325
DEC1: C5.1 U1.C1 | length 2.1
  Top Layer w0.254: U1.C1 20.715,-2.25 21.658,-1.306 C5.1
DEC3: C11.1 U1.D23 | length 1.6
  Top Layer w0.145: C11.1 12.985,-2.325 13.95,-2.325
  Top Layer w0.15: 13.95,-2.325 14.064,-2.325 14.389,-2 U1.D23
DEC4_6: C15.2 C16.1 L3.1 U1.B5 U1.E24 | length 11
  Top Layer w0.145: v1(13.382,-1.871) 13.774,-1.871 U1.E24
  Top Layer w0.25: U1.B5 19.145,-2.826 20.224,-3.905 20.224,-4.797 20.291,-4.863 L3.1 L3.1
  Bottom Layer w0.145: v1(13.382,-1.871) 13.76,-2.25 18.517,-2.25 v1(19.631,-3.363)
GND: C2.2 C3.1 C4.1 C5.2 C6.2 C7.2 C8.2 C9.2 C11.2 C12.2 C13.2 C14.2 C15.1 C16.2 C17.2 C18.2 C19.2 C20.2 C21.1 C22.1 C23.1 C24.1 C25.2 C26.1 C27.1 C28.1 C29.2 D1.1 FB2.2 GND1.1 GND2.1 GND3.1 GND4.1 J2.3 P1.3 P1.5 P1.9 SW1.2 SW2.2 U1.74 U1.B7 U1.B15 U1.F23 X1.2 | length 40.1
  Top Layer w0.127: SW1.2@9.517,4.77 SW1.2@9.517,4.895
  Top Layer w0.145: C3.1 12.759,-1.395 14.29,-1.395 U1.F23
  Top Layer w0.203: 7.391,-4.331 7.772,-4.331 ccw(c7.772,-3.48) v1@8.623,-3.48 ; v1(11.836,2.21) 12.169,2.21 12.979,1.4 C9.2 ; C22.1 28.087,-1.58 v1(28.245,-1.422) ; v1(28.524,1.829) 28.524,2.286 28.829,2.591 C23.1 29.027,2.401 C24.1 ; C21.1 29.204,-2.89 v1(29.667,-3.353)
  Top Layer w0.25: U1.F23 15.645,-1.5 U1.74@16.464,-0.681 ; U1.74 18.645,-1.5 U1.B7
  Top Layer w0.254: C2.2 13.568,-4.6 13.163,-4.6 X1.2 12.954,-5.332 13.942,-5.332 14.192,-5.082 ; C8.2 15.494,4.378 v1@15.494,4.826 ; U1.B15 16.645,-0.5 U1.74 ; C7.2 18.186,4.632 v1(18.186,4.953) ; C15.1 18.836,-5.501 18.999,-5.664 21.107,-5.664 ; 19.38,-4.115 C16.2 19.557,-4.212 v1@19.557,-5.359 ; C19.2 21.336,2.87 21.539,2.667 21.92,2.667 ; C20.2 22.307,4.017 22.064,3.775 22.022,3.775 v1(22.022,3.302) 22.047,3.327 23.343,3.327 23.444,3.226 24.486,3.226 24.71,3.001 C6.2 ; 23.647,-4.699 23.647,-4.647 24.232,-4.062 v1(24.232,-4.039) ; 23.774,-1.651 23.774,-1.727 24.105,-2.057 ; 24.536,-2.819 24.536,-2.921 24.993,-3.378 C18.2 25.318,-3.677 25.603,-3.962
  Top Layer w0.305: 10.02,-2.286 cw(c10.82,-2.286) 10.921,-1.492
  Bottom Layer w0.145: v1(29.54,-0.076) 30.293,0.677 31.464,0.677 J2.3@32.131,0.01
  other v1: 24.79,-5.74 22.022,-5.715 5.436,-5.613 6.147,-5.608 19.456,-5.512 30.251,-5.486 23.317,-5.334 28.677,-5.309 27.026,-4.877 16.434,-4.775 25.933,-4.724 14.304,-4.711 18.771,-4.039 5.537,-3.632 6.858,-3.556 8.458,-3.556 10.894,-2.311 11.825,-2.275 24.409,-2.032 10.257,-2.02 15.345,-1.8 16.545,-1.8 17.745,-1.8 18.945,-1.8 23.52,-1.382 8.687,-1.27 5.436,-0.965 15.345,-0.762 16.545,-0.762 17.745,-0.762 18.945,-0.762 6.858,-0.508 10.592,0.178 15.345,0.508 16.891,0.762 17.745,0.762 18.945,0.762 28.575,1.092 10.617,1.257 16.891,1.8 17.745,1.8 18.945,1.8 5.41,1.981 7.95,2.21 10.897,2.743 6.858,3.048 10.16,3.15 20.676,3.378 7.899,3.531 25.07,3.734 26.264,4.42 10.643,4.648 12.929,4.763 15.494,4.763 12.014,5.893 5.436,5.969 6.731,7.01
LED1: R3.1 U1.L1 | length 6.2
  Top Layer w0.127: U1.L1 20.806,-0.25 21.25,0.193 26.299,0.193 R3.1
LED2_B: R6.1 U1.U1 | length 7.5
  Top Layer w0.127: U1.U1 20.395,1.214 20.653,0.955 25.444,0.955 25.686,1.197 25.686,1.828 26.41,2.553 R6.1
LED2_G: R5.1 U1.R1 | length 6.9
  Top Layer w0.127: U1.R1 20.444,0.701 25.549,0.701 25.94,1.092 25.94,1.723 26.215,1.998 R5.1
LED2_R: R4.1 U1.N1 | length 6.3
  Top Layer w0.127: U1.N1 20.947,0.25 21.145,0.447 25.654,0.447 R4.1@26.358,1.151
NetC1_2: C1.2 X1.4 | length 0.9
  Top Layer w0.254: C1.2 11.156,-4.008 X1.4
NetC3_2: C3.2 L1.1 U1.H23 | length 2.5
  Top Layer w0.145: 12.585,-0.766 12.59,-0.771 C3.2@12.702,-0.882 ; C3.2 12.708,-1.105 14.29,-1.105 U1.H23
  Top Layer w0.508: L1.1@12.145,-0.771 12.59,-0.771
NetC9_1: C9.1 U1.N24 | length 1.1
  Top Layer w0.25: C9.1 13.49,0.579 13.819,0.25 U1.N24
NetC13_1: C13.1 U1.A18 | length 0.9
  Top Layer w0.25: U1.A18 15.895,-3.971 C13.1@16.026,-4.101
NetC20_1: C20.1 U1.AC5 | length 4.2
  Top Layer w0.184: U1.AC5 19.27,2.875 20.721,2.875 21.368,2.228 22.371,2.228 C20.1
NetD+_1: D+.1 J1.3 SB4.2 | length 7
  Top Layer w0.2: SB4.2 34.351,0.65 cw(c34.351,-0.268) v1(35,0.381) ; v1(35.941,-0.508) ccw(c37.144,0.695) 37.144,-1.006 J1.3
  Bottom Layer w0.2: D+.1@35.077,0.381 35.966,-0.508 v1@36.043,-0.508
NetD-_1: D-.1 J1.2 SB3.2 | length 7
  Top Layer w0.2: SB3.2 34.351,-0.65 ccw(c34.351,0.268) v1(35,-0.381) ccw(c35,-0.265) 35.082,-0.347 35.941,0.512 cw(c37.144,-0.691) 37.144,1.01 J1.2
NetFB2_1: FB2.1 J1.4 UGND.1 | length 12.4
  Top Layer w0.508: FB2.1 31.603,-3.246 32.207,-2.642 33.63,-2.642 v1(34.138,-3.15) 34.483,-3.495 J1.4@39.853,-3.495
  Bottom Layer w0.508: v1(34.138,-3.15) 34.138,-3.112 UGND.1
NetL2_1: L2.1 L3.2 | length 1
  Top Layer w0.25: L3.2@22.243,-4.735 22.276,-4.702 L2.1@22.276,-3.708
NetL2_2: L2.2 U1.B3 | length 3.2
  Top Layer w0.25: U1.B3 19.768,-2.75 20.204,-3.186 21.031,-3.186 21.859,-2.358 L2.2@22.276,-2.358
NetL4_2: L4.2 U1.AB2 | length 4.6
  Top Layer w0.203: U1.AB2 20.63,2.5 21.222,1.908 23.151,1.908 23.783,2.54 L4.2
NetLD1_1: LD1.1 R3.2 | length 4.9
  Top Layer w0.127: R3.2 26.98,-0.046 27.33,-0.396 27.33,-2.671 27.432,-2.772 27.432,-2.781 27.72,-3.069 27.72,-4.064 LD1.1
NetLD2_1: LD2.1 R4.2 | length 4
  Top Layer w0.127: R4.2 27.703,1.874 27.703,2.836 28.403,3.537 28.403,3.993 28.825,4.414 LD2.1
NetLD2_2: LD2.2 R5.2 | length 1.9
  Top Layer w0.127: R5.2 27.449,2.466 27.449,3.619 LD2.2
NetLD2_3: LD2.3 R6.2 | length 1.8
  Top Layer w0.127: R6.2 27.104,2.968 27.104,3.993 27.525,4.414 LD2.3
NetSB1_2: SB1.2 SB2.1 U1.Y2 | length 7.6
  Top Layer w0.203: U1.Y2 20.091,2 20.233,2.142 20.521,2.142 21.085,1.578 23.498,1.578 v1(23.698,1.778)
  Bottom Layer w0.254: SB2.1@22.606,3.681 23.362,3.681 ; v1(23.698,1.778) 23.38,2.096 23.38,3.663 23.362,3.681 ; SB1.2 23.907,3.681 23.692,3.681 23.362,3.681
P0.00/XL1: C17.1 U1.D2 X2.1 | length 6.3
  Top Layer w0.127: U1.D2 20.036,-1.859 20.634,-1.859 21.606,-0.887 24.402,-0.887 C17.1 25.394,-0.894 X2.1
P0.01/XL2: C18.1 U1.F2 X2.2 | length 10.5
  Top Layer w0.127: U1.F2 20,-1.605 20.529,-1.605 21.565,-0.569 26.426,-0.569 26.568,-0.711 26.568,-2.007 25.97,-2.605 X2.2 25.888,-2.839 C18.1
P0.02: 0.02.1 U1.A12 | length 5.2
  Top Layer w0.127: 0.02.1@15.875,-7.62 15.875,-7.163 17.646,-5.391 17.646,-3.792 17.395,-3.541 U1.A12
P0.04: 0.04.1 U1.J1 | length 11
  Top Layer w0.127: U1.J1 20.666,-0.75 21.355,-0.061 26.636,-0.061 27.076,-0.501 27.076,-2.946 27.28,-3.15 v1(27.28,-3.251)
  Bottom Layer w0.127: v1(27.28,-3.251) 27.28,-3.22 0.04.1
P0.09: 0.09.1 C28.2 U1.L24 | length 11.9
  Top Layer w0.127: v1(9.83,2.413) 10.016,2.227 11.073,2.227 11.535,1.765 12.201,1.765 12.462,1.504 12.462,0.542 12.75,0.253 13.369,0.253 13.873,-0.25 U1.L24 ; 0.09.1@10.795,7.188 10.795,7.62
  Bottom Layer w0.127: v1(9.83,2.413) 9.652,2.591 9.652,4.869 10.295,5.512 10.295,7.12 10.795,7.62
P0.10: 0.10.1 C29.1 U1.J24 | length 12.8
  Top Layer w0.127: 0.10.1@8.255,7.188 8.255,7.62 ; v1(9.195,2.413) 9.207,2.413 9.647,1.973 10.968,1.973 11.43,1.511 12.096,1.511 12.208,1.399 12.208,0.437 12.645,-0.001 13.264,-0.001 13.564,-0.3 13.564,-0.382 13.895,-0.714 U1.J24
  Bottom Layer w0.127: 8.255,7.62 8.755,7.12 8.755,5.512 9.398,4.869 9.398,2.616 v1(9.195,2.413)
P0.11: 0.11.1 U1.T2 | length 1.9
  Top Layer w0.127: U1.T2 19.895,1.444 v1(19.938,1.487)
  Bottom Layer w0.25: 0.11.1@19.685,2.794 19.938,2.541 v1(19.938,1.487)
P0.13: 0.13.1 U1.AD8 | length 12.4
  Top Layer w0.15: U1.AD8 18.395,3.467 20.442,5.514 24.803,5.514 25.357,6.068 27.455,6.068 28.575,7.188 28.575,7.62
P0.14: 0.14.1 U1.AC9 | length 0.5
  Top Layer w0.127: U1.AC9 18.589,2.75 v1(18.632,2.793)
  Bottom Layer w0.25: v1(18.632,2.793) v1(18.632,2.793)
P0.15: 0.15.1 U1.AD10 | length 10.3
  Top Layer w0.15: U1.AD10 17.895,3.358 20.328,5.791 24.689,5.791 26.035,7.137 26.035,7.62
P0.17: 0.17.1 U1.AD12 | length 8.2
  Top Layer w0.15: U1.AD12 20.213,6.068 22.451,6.068 23.495,7.112 23.495,7.62
P0.20: 0.20.1 U1.AD16 | length 7.5
  Top Layer w0.127: U1.AD16 16.395,3.636 16.789,4.03 16.789,5.054 17.501,5.766 19.535,5.766 20.955,7.185 20.955,7.62
P0.22: 0.22.1 U1.AD18 | length 5.4
  Top Layer w0.127: U1.AD18 15.895,3.495 16.535,4.135 16.535,5.159 17.323,5.947 17.323,6.02 18.415,7.112 18.415,7.62
P0.24: 0.24.1 U1.AD20 | length 4.9
  Top Layer w0.127: U1.AD20 15.395,3.355 16.281,4.24 16.281,7.214 15.875,7.62
P0.26: 0.26.1 U1.G1 | length 11.5
  Top Layer w0.127: U1.G1 20.525,-1.25 21.46,-0.315 26.531,-0.315 26.822,-0.606 26.822,-3.505 v1(26.67,-3.658)
  Bottom Layer w0.127: v1(26.67,-3.658) 27.012,-4 0.26.1
P0.29: 0.29.1 U1.A10 | length 4.6
  Top Layer w0.127: U1.A10 17.9,-3.255 17.9,-7.105 0.29.1@18.415,-7.62
P0.31: 0.31.1 U1.A8 | length 6.2
  Top Layer w0.127: U1.A8 18.395,-3.525 18.154,-3.766 18.154,-5.429 18.771,-6.045 19.812,-6.045 20.955,-7.188 0.31.1@20.955,-7.62
P1.00: 1.00.1 U1.AD22 | length 6.6
  Top Layer w0.127: 13.335,7.62 14.875,6.08 15.866,6.08 16.027,5.919 16.027,4.345 14.931,3.25 U1.AD22
P1.01: 1.01.1 U1.Y23 | length 1.6
  Top Layer w0.127: v1(14.357,2.477) 14.395,2.439 U1.Y23
  Bottom Layer w0.127: v1(14.357,2.477) 14.674,2.794 1.01.1@15.367,2.794
P1.02: 1.02.1 U1.W24 | length 4.2
  Top Layer w0.127: v1(12.141,3.321) 12.771,3.321 13.106,2.985 13.106,2.434 13.79,1.75 U1.W24
  Bottom Layer w0.127: v1(12.141,3.321) 13.179,3.321 1.02.1
P1.04: 1.04.1 U1.U24 | length 3.8
  Top Layer w0.127: v1(12.624,2.845) 12.624,2.557 13.895,1.286 U1.U24
  Bottom Layer w0.127: v1(12.624,2.845) 12.624,2.376 1.04.1
P1.07: 1.07.1 U1.P23 | length 2.3
  Top Layer w0.127: v1(14.352,0.013) 14.395,0.056 U1.P23
  Bottom Layer w0.127: v1(14.352,0.013) 14.352,0.852 1.07.1
P1.10: 1.10.1 U1.A20 | length 10.6
  Top Layer w0.127: 1.10.1@8.255,-7.62 8.255,-7.518 9.694,-6.08 11.976,-6.08 12.23,-5.826 13.954,-5.826 14.208,-5.572 15.282,-5.572 15.739,-5.114 15.739,-4.406 15.395,-4.062 U1.A20
P1.11: 1.11.1 U1.B19 | length 0.5
  Top Layer w0.145: v1(15.158,-2.793) 15.201,-2.75 U1.B19
P1.13: 1.13.1 U1.A16 | length 9.8
  Top Layer w0.127: 1.13.1@10.795,-7.62 10.795,-7.188 11.633,-6.35 12.065,-6.35 12.335,-6.08 14.059,-6.08 14.313,-5.826 16.494,-5.826 17.136,-5.183 17.136,-4.219 17.138,-4.216 17.138,-4.003 16.395,-3.259 U1.A16
P1.15: 1.15.1 U1.A14 | length 7.5
  Top Layer w0.127: 1.15.1@13.335,-7.62 13.335,-7.163 14.418,-6.08 16.599,-6.08 17.392,-5.286 17.392,-3.898 16.895,-3.4 U1.A14
RESET: C27.2 P1.10 R2.1 SW2.1 U1.AC13 U1.AC15 U1.AC17 U1.AC19 U1.AC21 | length 29.2
  Top Layer w0.127: SW2.1@7.913,1.07 7.366,1.617 7.366,4.123 7.913,4.67 8.964,3.619 10.452,3.619 v1(10.617,3.785) ; C27.2 14.026,4.173 v1(14.084,4.115) 14.084,4.539 R2.1 ; v1@14.067,3.942 14.067,3.096 14.241,2.922 14.973,2.922 U1.AC21 U1.AC19 U1.AC17 U1.AC15 U1.AC13
  Bottom Layer w0.127: v1(10.617,3.785) 13.754,3.785 v1(14.084,4.115) 14.8,4.115 15.207,3.708 15.374,3.708 15.84,3.242 15.84,0.394 16.488,-0.254 19.875,-0.254 20.535,-0.914 20.535,-1.943 21.133,-2.54 P1.10
RF: C4.2 C25.1 L1.2 R1.1 | length 7.3
  Top Layer w0.889: 6.909,-5.004 7.772,-5.004 ccw(c7.772,-3.48) 9.296,-3.48 9.296,-2.286 cw(c10.82,-2.286) 10.82,-0.762 11.227,-0.762
SW1: SW1.1 U1.R24 | length 5.1
  Top Layer w0.127: SW1.1 11.692,3.13 13.567,1.255 13.567,1.114 U1.R24@13.895,0.786
SWDCLK: J2.4 P1.4 pad.3@33.655,-5.08 SWDCLK.1 U1.AA24 | length 51
  Top Layer w0.127: v1(13.843,5.893) 12.637,5.893 12.208,5.463 12.208,4.243 13.36,3.09 13.36,2.539 13.65,2.25 U1.AA24
  Bottom Layer w0.127: P1.4 21.336,1.27 20.066,0 16.593,0 16.094,0.499 16.094,3.347 15.582,3.86 15.479,3.962 15.312,3.962 14.8,4.475 14.8,4.92 14.521,5.198 14.257,5.198 13.999,5.456 13.999,5.736 v1(13.843,5.893) 14.03,6.08 30.954,6.08 33.744,3.289 33.744,2.527 32.842,1.626 32.842,-0.686 J2.4 32.843,-1.27 33.655,-2.082 33.655,-5.08 33.655,-5.56 33.655,-6.01
SWDIO: J2.2 P1.2 pad.3@33.655,5.08 SWDIO.1 U1.AC24 | length 44.3
  Top Layer w0.127: U1.AC24 13.614,3.031 13.614,3.196 12.462,4.348 12.462,5.197 12.717,5.452 14.253,5.452 v1(14.44,5.639) ; v1(33.249,3.124) 33.249,5.604 33.655,6.01
  Bottom Layer w0.127: P1.2@21.819,2.54 21.125,2.54 20.535,1.951 20.535,0.829 19.961,0.254 16.699,0.254 16.348,0.604 16.348,3.452 15.584,4.216 15.417,4.216 15.054,4.58 15.054,5.025 v1(14.44,5.639) 14.627,5.826 30.848,5.826 33.249,3.425 v1(33.249,3.124) 33.249,2.398 J2.2@32.131,1.28 ; SWDIO.1@33.655,5.639 33.655,6.01
VBUS: C22.2 FB1.2 R7.2 | length 2.5
  Top Layer w0.381: R7.2@28.114,-0.855 28.622,-0.855 28.867,-1.1 28.867,-1.68 28.657,-1.89 C22.2 ; C22.2 FB1.2
VBUS': C21.2 C23.2 C24.2 D1.4 FB1.1 J1.1 J2.5 VBUS1.1 VBUS2.1 | length 35.5
  Top Layer w0.381: D1.4 29.718,1.213 v1(29.718,3.429) ; FB1.1 C21.2 30.15,-2.718 30.988,-1.88 31.008,-1.9 v1(32.85,-1.9) 33,-1.9 33.25,-1.65 v1(34,-1.65) ; v1(31.115,4.902) 31.824,4.902 32.537,4.189 32.537,2.743 33.452,1.829 v1(33.909,1.829) 34.684,2.603 37.351,2.603 38.257,3.51 J1.1
  Bottom Layer w0.381: VBUS1.1@28.575,-7.62 29.185,-7.01 29.693,-7.01 31.547,-5.156 31.547,-3.203 v1(32.85,-1.9) ; v1(29.718,3.429) 31.115,4.826 v1(31.115,4.902) ; v1(34,-1.65) 34.175,-1.475 34.175,1.563 v1(33.909,1.829) 34.33,2.25 VBUS2.1
VBUS_nRF: C19.1 R7.1 SB2.2 U1.AD2 | length 12.9
  Top Layer w0.25: U1.AD2 19.895,3.36 20.879,4.343 21.92,4.343 v1(21.971,4.394)
  Top Layer w0.254: v1(27.955,0.925) 27.955,0.858 28.114,0.699 R7.1
  Bottom Layer w0.254: v1(21.971,4.394) 22.598,4.394 SB2.2 23.335,5.131 24.787,5.131 26.413,3.505 26.949,3.505 27.381,3.073 27.381,1.499 v1(27.955,0.925)
VDD_nRF: "VDD nRF.1" "VDD OUT.1" C6.1 C7.1 C8.1 C12.1 C14.1 J2.1 L4.1 LD1.2 LD2.4 P1.1 R2.2 SB1.1 U1.A22 U1.AD14 U1.AD23 U1.B1 U1.W1 | length 78.4
  Top Layer w0.203: U1.W1 20.413,1.75 20.915,1.247 24.692,1.247 C6.1
  Top Layer w0.25: U1.AD23 14.395,3.513 14.661,3.779 C8.1@14.661,4.129 ; C8.1 14.676,4.338 14.992,4.654 14.992,4.97 15.406,5.385 v1(15.583,5.385) ; C12.1 14.869,-4.963 v1(15.037,-5.131) ; C12.1@14.895,-4.101 U1.A22 ; U1.AD14 16.895,3.397 17.201,3.703 v1@17.201,4.668 ; U1.B1 20.77,-2.75 21.666,-1.854 22.835,-1.854 25.146,-4.166 25.146,-4.877
  Top Layer w0.254: L4.1 24.593,4.531 25.519,4.531 25.911,4.924 26.801,4.924 v1(26.822,4.902) 26.822,4.191 v1(25.908,3.277) 25.908,2.565 25.095,1.753 C6.1 ; v1(24.257,-4.75) 25.019,-4.75 26.035,-5.766 ; 26.035,-7.442 26.035,-5.766 ; v1@29.432,4.095 28.02,2.683 28.02,1.742 27.451,1.173 27.451,0.422 27.648,0.225 27.648,-2.539 28.626,-3.517 28.626,-4.482 27.342,-5.766 26.035,-5.766
  Bottom Layer w0.203: v1@29.464,4.14 29.108,3.785 29.108,2.997 30.188,1.918 31.636,1.918 J2.1
  Bottom Layer w0.25: v1(15.583,5.385) 15.708,5.51 17.374,5.51 ; v1(17.348,4.699) 17.348,5.485 17.374,5.51 ; v1@29.464,4.14 29.083,4.521 27.203,4.521 v1(26.822,4.902) 26.215,5.51 17.374,5.51
  Bottom Layer w0.254: v1(15.037,-5.131) 15.922,-6.016 18.72,-6.016 ; 18,-3 18.494,-3 19.304,-3.81 19.304,-4.536 18.72,-5.12 18.72,-6.016 ; SB1.1@24.028,4.376 24.671,4.376 v1(24.689,4.394) ; v1(24.257,-4.75) 21.591,-4.75 20.325,-6.016 18.72,-6.016 ; P1.1@25.648,2.54 25.908,2.8 v1(25.908,3.277)
  other v1: 29.464,4.039
XC1: C1.1 U1.B24 X1.1 | length 5.7
  Top Layer w0.127: C1.1 10.749,-4.578 X1.1 X1.1@10.86,-5.071 ; X1.1@11.242,-4.93 11.262,-4.95 11.262,-5.071 11.989,-4.344 11.989,-3.455 12.138,-3.305 13.34,-3.305 U1.B24
XC2: C2.1 U1.A23 X1.3 | length 2.1
  Top Layer w0.15: X1.3@12.692,-3.78 12.932,-4.02 13.568,-4.02 13.625,-4.02 U1.A23
pads on no net: Fid1.0 Fid2.0 J2.0 J2.6 J2.7 J2.8 J2.9 J2.10 P1.6 P1.7 P1.8 SW1.0 U1.AC11 U1.B9 U1.B11 U1.B13 U1.B17 U1.H2 U1.K2 U1.M2 U1.P2 U1.T23 U1.V23

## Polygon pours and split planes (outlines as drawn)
GND on Bottom Layer "Bottom_Layer-GND" (solid, remove dead copper, pour order 37): -2.54,-10.16 -2.54,10.16 48.26,10.16 48.26,-10.16
GND on Top Layer "Top_Layer-GND" (solid, remove dead copper, pour order 39): -2.54,-10.226 -2.54,10.16 48.26,10.16 48.26,-10.226

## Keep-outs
Keep-Out Layer:
  lines w0.15: 30.027,-7.62 31.637,-6.01 32.537,-6.01 ; 30.027,7.62 31.637,6.01 32.537,6.01 ; 34.773,-6.01 46.039,-6.01 46.039,6.01 34.773,6.01
  lines w0.152: 4.953,-7.62 0,-7.62 0,7.62 4.953,7.62

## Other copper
Top Layer:
  rectangle net GND: 22.25,-7.294 24.765,-5.893
  rectangle net GND: 5.156,-7.29 6.579,-5.842
  rectangle net GND: 5.156,5.842 6.579,7.29
Bottom Layer:
  rectangle net GND: 22.25,-7.294 24.765,-5.893
  rectangle net GND: 5.156,-7.29 6.579,-5.842
  rectangle net GND: 5.156,5.842 6.579,7.29
  rectangle net GND: 12.395,-4.039 14.351,-2.591

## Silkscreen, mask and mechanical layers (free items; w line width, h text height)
Top Overlay:
  text "'.PCBNumber'" at 35.992,2.616 h2.16 r270
  text "'.PCBRevision'" at 34.9,2.464 h0.69 r270
  text "RESET" at 5.893,-0.635 h0.69
  text "VDD / OUT" at 25.241,-6.248 h0.51
Bottom Overlay:
  lines w0.2: 5.319,-2.5 ccw(c6.319,-2.5) 6.319,-3.5 11.319,-3.5 ccw(c11.319,-2.5) 12.319,-2.5 12.319,2.5 ccw(c11.319,2.5) 11.319,3.5 6.319,3.5 ccw(c6.319,2.5) 5.319,2.5 5.319,-2.5
  text "LABEL" at 8.342,-2.281 h1.02 r270
  text "VDD / nRF" at 17.137,-5.455 h0.51 r270
  text "nRF52840-Dongle" at 0.813,-7.188 h2.41 r270
Board Outline:
  the board outline again, w0.152
Bottom Assembly:
  region: 45.57,1.557 45.57,1.836 43.609,1.836 43.609,1.557
  region: 45.57,3.236 45.57,3.516 43.609,3.516 43.609,3.236
  region: 41.649,-2.644 41.369,-2.644 41.369,-3.203 41.649,-3.203
  rectangle: 43.61,-3.483 43.89,-1.522
  rectangle: 45.29,-3.483 45.57,-1.522
  region: 45.57,-1.803 45.57,-1.523 43.609,-1.523 43.609,-1.803
  region: 45.57,-3.483 45.57,-3.203 43.609,-3.203 43.609,-3.483
  region: 40.529,1.557 40.529,1.836 38.569,1.836 38.569,1.557
  region: 40.529,3.237 40.529,3.517 38.569,3.517 38.569,3.237
  region: 38.849,3.517 38.57,3.517 38.57,1.557 38.849,1.557
  region: 40.529,3.517 40.249,3.517 40.249,1.557 40.529,1.557
  region: 43.888,3.517 43.609,3.517 43.609,1.557 43.888,1.557
  region: 45.57,3.517 45.29,3.517 45.29,1.557 45.57,1.557
  region: 40.529,-1.523 40.249,-1.523 40.249,-1.803 40.529,-1.803
  region: 39.97,2.956 39.129,2.956 39.129,2.117 39.97,2.117
  region: 45.009,2.956 44.17,2.956 44.17,2.117 45.009,2.117
  region: 45.009,-2.083 44.17,-2.083 44.17,-2.923 45.009,-2.923
Placement:
  lines w0.152: 32.039,-6.01 32.039,6.01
